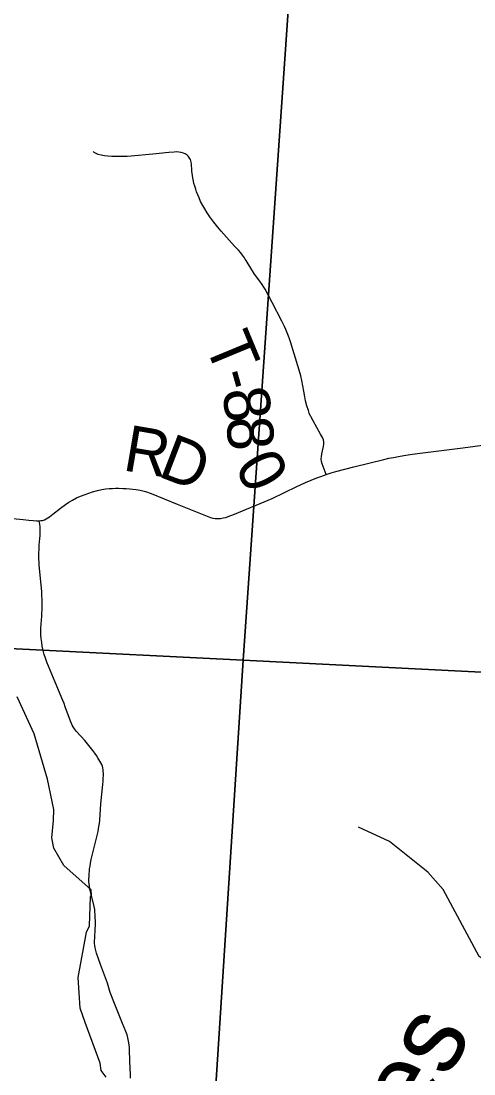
# Model space of a CAD drawing. Extents: x 0 to 34, y 0 to 22.
# Drawn here: x 4.884 to 5.443, y 17.839 to 19.136 of the extents above; entities that cross this region are included whole.
import ezdxf

# ---------------------------------------------------------------- set-up
doc = ezdxf.new("R2010")
doc.units = 0
for name, color, linetype in [('GM_X_County_Road', 7, 'Continuous'), ('GM_X_County_Road_Text', 7, 'Continuous'), ('GM_X_Minor_River', 7, 'Continuous'), ('GM_X_Minor_River_Text', 7, 'Continuous'), ('GM_X_Section', 7, 'Continuous'), ('GM_X_Township_Road', 7, 'Continuous'), ('GM_X_Township_Road_Text', 7, 'Continuous')]:
    doc.layers.add(name, color=color, linetype=linetype)

msp = doc.modelspace()

# ---------------------------------------------------------------- linework, layer by layer
at = {"layer": 'GM_X_County_Road'}
for points in [[(5.2338, 18.5668), (5.2347, 18.5673), (5.2417, 18.5702), (5.2489, 18.5731), (5.2548, 18.5753), (5.2604, 18.5773), (5.2663, 18.5791), (5.2721, 18.5807), (5.2944, 18.5866), (5.3313, 18.5957), (5.3374, 18.5971), (5.3434, 18.5983), (5.3496, 18.5995), (5.3561, 18.6006), (5.3639, 18.6017), (5.3728, 18.6029), (5.4287, 18.6099), (5.4807, 18.617), (5.5191, 18.6222), (5.5356, 18.6246), (5.5479, 18.6266), (5.555, 18.6281), (5.5593, 18.6291)], [(4.8568, 18.5245), (4.8868, 18.5216), (4.8938, 18.5209), (4.899, 18.5203), (4.9031, 18.5201), (4.9065, 18.5201), (4.9084, 18.5203), (4.9105, 18.5207), (4.9128, 18.5215), (4.915, 18.5226), (4.917, 18.5238), (4.919, 18.5252), (4.9232, 18.5284), (4.9328, 18.5356), (4.9388, 18.5401), (4.943, 18.543), (4.9476, 18.5457), (4.9525, 18.5484), (4.9574, 18.5505), (4.9629, 18.5527), (4.9675, 18.5543), (4.9722, 18.5557), (4.9781, 18.5573), (4.9835, 18.5586), (4.9885, 18.5594), (4.9925, 18.5599), (4.9966, 18.5601), (5.0006, 18.5602), (5.0045, 18.5602), (5.0094, 18.5601), (5.0136, 18.5599), (5.0181, 18.5595), (5.022, 18.5591), (5.026, 18.5586), (5.0311, 18.5578), (5.0375, 18.5561), (5.0446, 18.5536), (5.0766, 18.5406), (5.1177, 18.5243), (5.1206, 18.5235), (5.1236, 18.523), (5.1264, 18.5229), (5.1298, 18.5231), (5.1332, 18.5236), (5.1366, 18.5244), (5.1396, 18.5253), (5.1473, 18.5281), (5.1937, 18.5476), (5.2243, 18.5624), (5.2338, 18.5668)], [(5.0191, 17.8336), (5.0188, 17.8394), (5.0186, 17.8447), (5.0179, 17.8674), (5.0176, 17.8711), (5.0173, 17.8748), (5.0167, 17.8793), (5.0159, 17.8832), (5.0147, 17.8872), (5.0133, 17.8911), (5.0093, 17.901), (4.9975, 17.9297), (4.9956, 17.9349), (4.9941, 17.9393), (4.9905, 17.9507), (4.9819, 17.9736), (4.9772, 17.9874), (4.9762, 17.9907), (4.9753, 17.994), (4.9749, 17.9969), (4.9747, 17.9994), (4.9747, 18.002), (4.9748, 18.007), (4.9754, 18.0167), (4.9757, 18.023), (4.9757, 18.0275), (4.9756, 18.0313), (4.9755, 18.0351), (4.9752, 18.0383), (4.9749, 18.0415), (4.9743, 18.0452), (4.9735, 18.0488), (4.9689, 18.0664), (4.9683, 18.0701), (4.968, 18.0728), (4.9678, 18.0759), (4.9678, 18.0789), (4.9679, 18.0823), (4.968, 18.0851), (4.9683, 18.0887), (4.9686, 18.0916), (4.9691, 18.0946), (4.9697, 18.0984), (4.9706, 18.1028), (4.979, 18.1375), (4.9796, 18.1406), (4.9801, 18.1437), (4.9806, 18.1475), (4.981, 18.1516), (4.9826, 18.1715), (4.9849, 18.1953), (4.9852, 18.1996), (4.9854, 18.2032), (4.9855, 18.2063), (4.9855, 18.2091), (4.9854, 18.2115), (4.9852, 18.2135), (4.9849, 18.2157), (4.9843, 18.2178), (4.9835, 18.2201), (4.9824, 18.2222), (4.9789, 18.2282), (4.9771, 18.231), (4.975, 18.2339), (4.9724, 18.2374), (4.9693, 18.2413), (4.966, 18.2453), (4.9625, 18.2494), (4.9525, 18.2607), (4.9501, 18.2637), (4.9483, 18.2664), (4.9472, 18.2683), (4.9461, 18.2706), (4.9451, 18.2733), (4.9386, 18.2912), (4.9371, 18.2952), (4.9354, 18.2989), (4.9261, 18.3212), (4.9158, 18.3459), (4.914, 18.3508), (4.9127, 18.3554), (4.9114, 18.3602), (4.9102, 18.3657), (4.9095, 18.3703), (4.909, 18.375), (4.9086, 18.3796), (4.9085, 18.3838), (4.9085, 18.388), (4.9087, 18.3929), (4.9095, 18.4026), (4.9097, 18.4064), (4.9099, 18.4105), (4.9101, 18.4168), (4.91, 18.4233), (4.9098, 18.4283), (4.9096, 18.4327), (4.9092, 18.4373), (4.9065, 18.4656), (4.9063, 18.4693), (4.9061, 18.4727), (4.9061, 18.4764), (4.9061, 18.4801), (4.9062, 18.4854), (4.9064, 18.4901), (4.9066, 18.4941), (4.907, 18.4983), (4.9074, 18.5021), (4.9077, 18.5062), (4.9076, 18.5095), (4.9074, 18.5127), (4.907, 18.5161), (4.9065, 18.5201)]]:
    msp.add_lwpolyline(points, dxfattribs=at)
at = {"layer": 'GM_X_Minor_River'}
for points in [[(4.963, 17.9021), (4.957, 17.92), (4.9543, 17.9576), (4.9648, 18.0135), (4.9686, 18.0211), (4.9697, 18.0568), (4.9708, 18.0591), (4.9704, 18.0656), (4.9368, 18.0955), (4.9246, 18.1168), (4.922, 18.1297), (4.9239, 18.151), (4.9246, 18.1646), (4.9166, 18.2019), (4.9003, 18.2577), (4.8791, 18.3033)], [(5.5139, 17.9476), (5.4945, 17.9531), (5.4488, 17.9836), (5.4046, 18.0661), (5.3855, 18.0873), (5.3382, 18.125), (5.3002, 18.1427)], [(4.9888, 17.8349), (4.9827, 17.8429), (4.9816, 17.852), (4.963, 17.9021)]]:
    msp.add_lwpolyline(points, dxfattribs=at)
at = {"layer": 'GM_X_Section'}
for points in [[(4.1716, 19.4188), (5.2288, 19.368), (5.1578, 18.3486), (4.1036, 18.4009)], [(5.2288, 19.368), (6.2595, 19.3129), (6.1942, 18.2962), (5.1578, 18.3486)], [(4.1036, 18.4009), (5.1578, 18.3486), (5.0921, 17.3266), (4.0444, 17.3771)], [(5.1578, 18.3486), (6.1942, 18.2962), (6.1312, 17.2799), (5.0921, 17.3266)]]:
    msp.add_lwpolyline(points, close=True, dxfattribs=at)
at = {"layer": 'GM_X_Township_Road'}
for points in [[(5.2416, 18.6481), (5.2411, 18.649), (5.2395, 18.6527), (5.2384, 18.6559), (5.2366, 18.6618), (5.235, 18.6678), (5.2339, 18.673), (5.2326, 18.6796), (5.2316, 18.6862), (5.2304, 18.6929), (5.2291, 18.6987), (5.2269, 18.7056), (5.2207, 18.7258), (5.2164, 18.7404), (5.2151, 18.7444), (5.2139, 18.7476), (5.2123, 18.7517), (5.2107, 18.7557), (5.209, 18.7595), (5.2074, 18.7629), (5.2058, 18.7659), (5.1935, 18.7892), (5.1849, 18.8053), (5.1834, 18.808), (5.1814, 18.8112), (5.1795, 18.8141), (5.1774, 18.817), (5.1721, 18.8241), (5.1615, 18.8406), (5.1605, 18.8423), (5.1595, 18.8439), (5.1583, 18.8457), (5.1572, 18.8472), (5.155, 18.8501), (5.1522, 18.8534), (5.1499, 18.8559), (5.1474, 18.8585), (5.131, 18.8768), (5.1265, 18.882), (5.1218, 18.8881), (5.1169, 18.8947), (5.1136, 18.8993), (5.1106, 18.9042), (5.1081, 18.9086), (5.1055, 18.9136), (5.1035, 18.9179), (5.102, 18.9215), (5.1005, 18.9254), (5.0994, 18.9285), (5.0982, 18.9321), (5.0972, 18.9356), (5.0965, 18.9385), (5.0958, 18.9425), (5.0953, 18.9455), (5.095, 18.9483), (5.0948, 18.9505), (5.0945, 18.9544), (5.0944, 18.9568), (5.0941, 18.9592), (5.0937, 18.9617), (5.0933, 18.9636), (5.0928, 18.9653), (5.0919, 18.9669), (5.0906, 18.9689), (5.0887, 18.9706), (5.0866, 18.972), (5.0842, 18.9731), (5.0815, 18.9739), (5.0787, 18.9743), (5.0758, 18.9745), (5.0728, 18.9743), (5.0664, 18.9738), (5.0465, 18.9716), (5.0197, 18.9693), (5.0147, 18.969), (5.0101, 18.9689), (5.0053, 18.9687), (5.001, 18.9687), (4.9958, 18.9689), (4.991, 18.9692), (4.9868, 18.9696), (4.9827, 18.9704), (4.9792, 18.9715), (4.9758, 18.9729), (4.9728, 18.9744)], [(5.2604, 18.5773), (5.2552, 18.5905), (5.2546, 18.5931), (5.2543, 18.5963), (5.2544, 18.5988), (5.255, 18.6026), (5.257, 18.6117), (5.2574, 18.6147), (5.2575, 18.6171), (5.2569, 18.6199), (5.2559, 18.6227), (5.2535, 18.627), (5.2441, 18.6431), (5.2425, 18.6461), (5.2416, 18.6481)]]:
    msp.add_lwpolyline(points, dxfattribs=at)

# ---------------------------------------------------------------- texts
at = {"layer": 'GM_X_County_Road_Text'}
for s, rotation, p in [('R', 350.3214, (5.0082, 18.5826)), ('D', 338.9366, (5.0513, 18.5755))]:
    msp.add_text(s, height=0.0568, rotation=rotation, dxfattribs=at).set_placement(p)
at = {"layer": 'GM_X_Minor_River_Text'}
msp.add_text('Drakes', height=0.09469, rotation=59.9948, dxfattribs=at).set_placement((5.2403, 17.5398))
at = {"layer": 'GM_X_Township_Road_Text'}
for s, rotation, p in [('T', 292.5216, (5.1097, 18.7386)), ('-', 285.7953, (5.1254, 18.701)), ('8', 279.6839, (5.1314, 18.6802)), ('8', 274.0676, (5.1371, 18.6471)), ('0', 297.5303, (5.1464, 18.588))]:
    msp.add_text(s, height=0.0568, rotation=rotation, dxfattribs=at).set_placement(p)

doc.saveas('drawing.dxf')
